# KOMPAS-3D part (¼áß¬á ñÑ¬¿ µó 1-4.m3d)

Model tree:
1. Эскиз:1
2. Операция выдавливания:24
     Толщина стенки 2 = 14; Расстояние 1 = 0.6
3. Эскиз:22
4. Операция выдавливания:25
     Толщина стенки 1 = 7; Толщина стенки 2 = 6; Расстояние 1 = 0.6; Расстояние 2 = 0.6
5. Эскиз:23
6. Операция выдавливания:26
     Толщина стенки 1 = 6; Толщина стенки 2 = 6; Расстояние 1 = 0.6
7. Эскиз:26
8. Вырезать элемент выдавливания:3
     Толщина стенки 1 = 7; Расстояние 1 = 10
